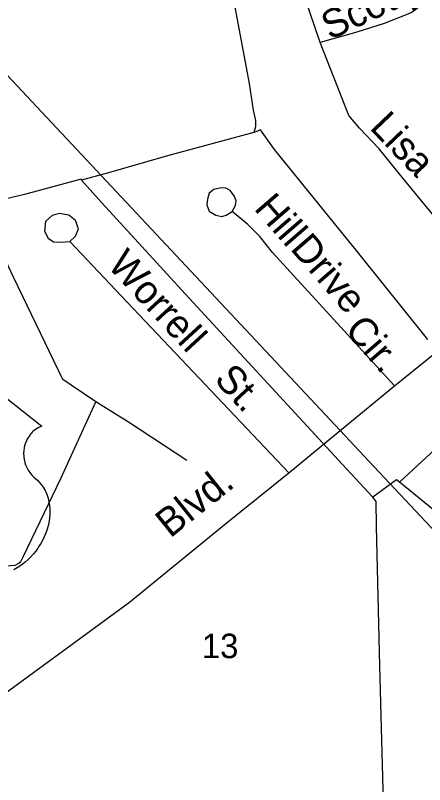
# Model space of a CAD drawing. Extents: x 2260773 to 2342389, y 552869 to 618546.
# Drawn here: x 2318179 to 2319547, y 594846 to 597420 of the extents above; entities that cross this region are included whole.
import ezdxf

# ---------------------------------------------------------------- set-up
doc = ezdxf.new("R2010")
doc.units = 0
for name, color, linetype in [('Exist Hydrographic Misc Water Feature', 7, 'Continuous'), ('Exist Road Non-System Type 51', 7, 'Continuous'), ('Exist Road Non-System Type 51 Label', 7, 'Continuous'), ('Exist Road Primary US Label', 7, 'Continuous'), ('Exist Road Primary US Shield CELL', 7, 'Continuous'), ('Exist Road Primary US UnDivided 4 Lane Attributed', 7, 'Continuous'), ('Exist Utilities Electrical Transmission Line', 7, 'Continuous')]:
    doc.layers.add(name, color=color, linetype=linetype)

msp = doc.modelspace()

# ---------------------------------------------------------------- linework, layer by layer
at = {"layer": 'Exist Hydrographic Misc Water Feature'}
for points in [[(2318813, 598477.7), (2318945.9, 598201.4), (2319042.5, 597984.5), (2318936.9, 597955.4), (2318832.9, 597926), (2318899.2, 597519.1), (2318960.7, 597191.8), (2318973.8, 597102.2), (2318982.2, 597068.1), (2318982.4, 597046.2), (2318976.5, 597028.1)], [(2318976.5, 597028.1), (2318687.3, 596949.1), (2318556.3, 596911.6), (2318490.3, 596893.2), (2318400.7, 596868.2)], [(2319557.6, 596334.7), (2319323, 596627.9), (2319045.6, 596971.1), (2318998.6, 597036.5), (2318982.8, 597030.4), (2318976.5, 597028.1)], [(2318400.7, 596868.2), (2318398.8, 596872.1), (2318209.4, 596819.9), (2318057.8, 596784.3)], [(2319373.8, 595807.2), (2319286.7, 595902.2), (2318746.6, 596488), (2318457.3, 596804.9), (2318400.7, 596868.2)], [(2318448.7, 596127), (2318366, 596182), (2318337.7, 596201.6), (2318174.3, 596541.7), (2318057.8, 596784.3)], [(2320799, 596168.2), (2320527.1, 596151.1), (2320235.5, 596128.1), (2319922, 596110.8), (2319748.3, 596100.9), (2319581.6, 595967.4), (2319463, 595857.9)], [(2317532.1, 595857.3), (2317642.8, 595776.6), (2317893.6, 595677.2), (2318130.4, 595584), (2318146.4, 595577.9), (2318164.4, 595578.4), (2318178.8, 595580.3), (2318190.5, 595586.7), (2318198.1, 595592.4), (2318200.1, 595596.6), (2318206.3, 595610.7), (2318331.6, 595870), (2318448.7, 596127)], [(2318752.5, 595930.3), (2318557.5, 596058.2), (2318448.7, 596127)], [(2319463, 595857.9), (2319452.8, 595865.9), (2319373.8, 595807.2)], [(2320857.6, 595171.5), (2320849.8, 595171.1), (2320581.8, 595146.5), (2320346.4, 595132), (2320104.2, 595331.1), (2319680.8, 595680.3), (2319463, 595857.9)], [(2319420.4, 594414.5), (2319411, 594746), (2319397.6, 595243.6), (2319386.4, 595709.2), (2319385.5, 595793.3), (2319373.8, 595807.2)]]:
    msp.add_lwpolyline(points, dxfattribs=at)
at = {"layer": 'Exist Road Non-System Type 51'}
msp.add_line((2319198, 597328.4), (2319046.6, 597773.4), dxfattribs=at)
for points in [[(2319573.8, 597480.6), (2319502.2, 597427.8), (2319411.6, 597392), (2319321, 597363.6), (2319198, 597328.4)], [(2319806.8, 596471.4), (2319475.1, 596874), (2319395.4, 596972.7), (2319329.2, 597041.7), (2319294, 597085), (2319198, 597328.4)], [(2318903.7, 596763.2), (2318915.5, 596783.3), (2318917.2, 596799.3), (2318911, 596815.3), (2318896.9, 596833.1), (2318882.7, 596841), (2318866.9, 596842.7), (2318842.9, 596836.5), (2318827, 596824.3), (2318821.2, 596804.3), (2318819.5, 596786.2), (2318827.6, 596764.3), (2318849.8, 596750.6), (2318869.7, 596746.8), (2318883.8, 596751), (2318903.7, 596763.2)], [(2318361, 596662.8), (2318380.8, 596681), (2318390.7, 596705.2), (2318380.3, 596733), (2318358.2, 596750.9), (2318326, 596756.4), (2318302.2, 596750.2), (2318280.4, 596729.9), (2318276.7, 596698), (2318288.9, 596674.1), (2318307.2, 596662.2), (2318331.1, 596660.6), (2318361, 596662.8)], [(2319447.1, 596180.4), (2319039, 596626.6), (2318996.5, 596680.1), (2318956.1, 596719.7), (2318903.7, 596763.2)], [(2319092.9, 595889.5), (2318553.2, 596460.5), (2318361, 596662.8)]]:
    msp.add_lwpolyline(points, dxfattribs=at)
at = {"layer": 'Exist Road Primary US Shield CELL'}
msp.add_lwpolyline([(2318138.7, 596148), (2318267.3, 596045.5), (2318264.2, 596044.4), (2318257.3, 596041), (2318251.7, 596037.7), (2318242.9, 596031.5), (2318239.1, 596028), (2318235.3, 596024.5), (2318231.8, 596020.7), (2318228.7, 596017.1), (2318225, 596011.9), (2318221.6, 596006.8), (2318218.4, 596001.1), (2318216, 595996.1), (2318212, 595985.8), (2318210.1, 595979.3), (2318208.9, 595973.7), (2318207.4, 595962.2), (2318207, 595956.8), (2318207, 595951.4), (2318207.3, 595945.7), (2318207.9, 595940.2), (2318208.8, 595934.5), (2318209.8, 595929.5), (2318211.4, 595923.3), (2318213.6, 595916.2), (2318216.4, 595909.3), (2318222.3, 595898.1), (2318229.9, 595886.7), (2318235.3, 595880.3), (2318240.6, 595874.9), (2318248.5, 595868.2), (2318252.8, 595864.4), (2318257.8, 595859.4), (2318265.8, 595850.1), (2318269.1, 595845.7), (2318272.4, 595840.7), (2318275.4, 595835.6), (2318278.4, 595830.2), (2318280.9, 595825.4), (2318285.4, 595814.4), (2318288.7, 595803.7), (2318290.2, 595798), (2318292.6, 595785.4), (2318293.5, 595779.2), (2318294.5, 595766.9), (2318294.5, 595752), (2318293.4, 595737.8), (2318290.8, 595721.4), (2318288.5, 595711.5), (2318285.2, 595700), (2318281.9, 595690), (2318276, 595675.4), (2318270.8, 595664.7), (2318264.1, 595652.3), (2318259.4, 595644.8), (2318254, 595636.7), (2318247.3, 595627.4), (2318239.4, 595617.6), (2318229.9, 595607.1), (2318222.2, 595599.5), (2318212.2, 595590.5), (2318206.1, 595585.5), (2318197.5, 595579), (2318185.6, 595571.1), (2318173.9, 595564.3)], dxfattribs=at)
at = {"layer": 'Exist Road Primary US UnDivided 4 Lane Attributed'}
msp.add_lwpolyline([(2317762.5, 594867.4), (2318064.2, 595092.6), (2318561.2, 595456.7), (2318882.3, 595719.8), (2319092.9, 595889.5), (2319264.7, 596030.6), (2319447.1, 596180.4), (2319806.8, 596471.4), (2319952.1, 596590.9), (2320303.8, 596881.5), (2320747.5, 597242.4), (2320844.3, 597319.9), (2321170.3, 597586.3), (2321303.6, 597697.8), (2321872.6, 598168.2)], dxfattribs=at)
at = {"layer": 'Exist Utilities Electrical Transmission Line'}
for points in [[(2317200.8, 598235.4), (2317419.2, 598002.6), (2319264.7, 596030.6)], [(2319264.7, 596030.6), (2319360.4, 595928.4), (2320817.7, 594376.5)]]:
    msp.add_lwpolyline(points, dxfattribs=at)

# ---------------------------------------------------------------- texts
at = {"layer": 'Exist Road Non-System Type 51 Label'}
for s, rotation, p in [('Scotty', 25.1518, (2319230.6, 597335.9)), ('Lisa', 313.7595, (2319360.3, 597041.7)), ('Hill', 310.9169, (2318974, 596772.2)), ('Drive', 310.9169, (2319095.4, 596637.9)), ('Worrell', 312.6632, (2318483.6, 596581.1)), ('Cir.', 310.9169, (2319276.8, 596365)), ('St.', 312.6632, (2318840.6, 596199))]:
    msp.add_text(s, height=95, rotation=rotation, dxfattribs=at).set_placement(p)
at = {"layer": 'Exist Road Primary US Label'}
msp.add_text('Blvd.', height=95, rotation=38.7487, dxfattribs=at).set_placement((2318696.8, 595668.6))
msp.add_text('13', height=82.02, dxfattribs=at).set_placement((2318802.8, 595268.9))

doc.saveas('drawing.dxf')
